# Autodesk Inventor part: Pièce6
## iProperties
Shininess: 64.0
Length Units: 11269
Angle Units: 11279
Time Units: 11290
Mass Units: 11283
Length Display Precision: 3
Angle Display Precision: 2
Compacted: True
Part Number: Pièce6
Document SubType Name: Modeling
Created: 2004-06
Material: Par défaut
Designer: laurent
Density: 0.0
Volumn: 0.0
Area: 0.0
PropertySet Name: Model Information
Control State: 0
Master: False
Checked Out: False
Author: laurent
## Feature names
1. Extrusion1
2. Balayage2
3. Balayage3
4. Révolution1 [Revolution]
5. Balayage4
6. Réseau rectangulaire1 [Rectangular Pattern]
7. Extrusion2
8. Extrusion3
9. Extrusion4
10. Balayage6
